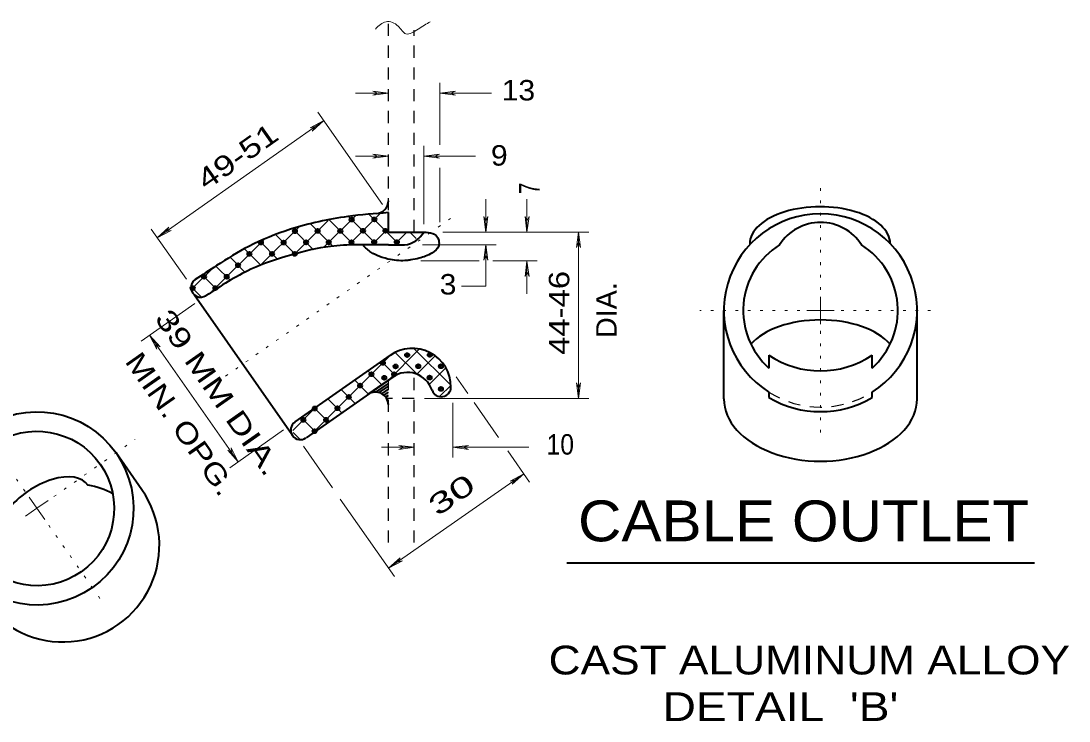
# Model space of a CAD drawing. Extents: x 312583 to 312854, y 144419 to 144597.
# Drawn here: x 312623.25 to 312662.22, y 144470.63 to 144496.66 of the extents above; entities that cross this region are included whole.
import ezdxf

# ---------------------------------------------------------------- set-up
doc = ezdxf.new("R2010")
doc.units = 0
doc.header["$LTSCALE"] = 0.3
doc.header["$PDMODE"] = 32
doc.header["$PDSIZE"] = 0.15
doc.linetypes.add('DOTTED', pattern=[1.5, 0.3, -1.2])
doc.linetypes.add('SHORT_DASHED', pattern=[2.7, 1.5, -1.2])
doc.layers.add('1', color=7, linetype='Continuous', lineweight=40)
doc.layers.add('2', color=7, linetype='Continuous', lineweight=13)

msp = doc.modelspace()

# ---------------------------------------------------------------- linework, layer by layer
at = {"layer": '1', "linetype": 'SHORT_DASHED', "lineweight": 25}
for p, q in [((312636.9103, 144488.8172), (312636.9103, 144496.6219)), ((312637.8686, 144488.8172), (312637.8686, 144496.3229)), ((312637.8686, 144477.2712), (312637.8686, 144483.5579)), ((312636.9103, 144477.2712), (312636.9103, 144483.2742)), ((312637.8686, 144482.6302), (312636.9103, 144482.6302))]:
    msp.add_line(p, q, dxfattribs=at)
at = {"layer": '1', "linetype": 'DOTTED', "lineweight": 13}
msp.add_line((312639.2256, 144489.3232), (312630.8459, 144483.4506), dxfattribs=at)
at = {"layer": '1', "lineweight": 13}
for p, q in [((312634.5106, 144488.2499), (312635.6836, 144489.4229)), ((312635.4306, 144488.3266), (312636.6189, 144489.5149)), ((312636.4656, 144488.3572), (312635.4383, 144489.3846)), ((312637.3166, 144488.3496), (312636.1896, 144489.4766)), ((312632.2106, 144487.6289), (312633.5753, 144488.9936)), ((312634.1273, 144488.1579), (312633.3529, 144488.9322)), ((312633.4066, 144487.9816), (312634.6716, 144489.2466)), ((312634.8403, 144488.2882), (312634.0123, 144489.1162)), ((312635.6299, 144488.3419), (312634.7253, 144489.2542)), ((312636.3046, 144488.3572), (312636.9103, 144488.9629)), ((312630.3476, 144486.6092), (312632.3026, 144488.5566)), ((312633.4449, 144487.9892), (312632.7013, 144488.7406)), ((312637.1326, 144488.3496), (312637.6003, 144488.8172)), ((312637.9376, 144488.5719), (312637.6923, 144488.8249)), ((312632.1416, 144487.6059), (312631.5589, 144488.1886)), ((312632.7856, 144487.8129), (312632.1263, 144488.4722)), ((312631.5743, 144487.3299), (312631.0223, 144487.8819)), ((312629.6039, 144486.7012), (312630.3936, 144487.4909)), ((312631.0299, 144487.0309), (312630.5009, 144487.5522)), ((312630.5086, 144486.7012), (312629.9873, 144487.2226)), ((312629.9413, 144486.4252), (312629.5963, 144486.7702)), ((312634.0813, 144481.3269), (312637.0253, 144484.2709)), ((312636.8873, 144483.2896), (312638.0679, 144484.4702)), ((312637.9759, 144483.5349), (312637.1479, 144484.3552)), ((312639.2409, 144483.1132), (312637.8456, 144484.4932)), ((312637.1633, 144483.4889), (312636.6496, 144484.0026)), ((312637.9683, 144483.5349), (312638.6506, 144484.2172)), ((312636.6726, 144483.1362), (312636.1513, 144483.6576)), ((312638.4359, 144483.1592), (312639.0493, 144483.7726)), ((312636.1743, 144482.7912), (312635.6606, 144483.3049)), ((312638.8116, 144482.6992), (312639.2409, 144483.1286)), ((312635.6759, 144482.4386), (312635.1546, 144482.9599)), ((312633.3529, 144481.4342), (312634.2193, 144482.3006)), ((312635.1776, 144482.0936), (312634.6639, 144482.6149)), ((312634.1886, 144481.3959), (312633.6673, 144481.9172)), ((312634.6869, 144481.7409), (312634.1656, 144482.2622)), ((312633.6059, 144481.1276), (312633.3683, 144481.3652))]:
    msp.add_line(p, q, dxfattribs=at)
at = {"layer": '1'}
for p, q in [((312636.9103, 144488.8172), (312636.9103, 144489.5379)), ((312636.9103, 144488.8172), (312638.2289, 144488.8172)), ((312636.9103, 144488.3419), (312637.5083, 144488.3419)), ((312633.3223, 144481.2886), (312629.6959, 144486.4789)), ((312649.3839, 144482.6149), (312649.3839, 144485.9039)), ((312656.5676, 144482.6149), (312656.5676, 144485.9039)), ((312636.9793, 144484.2326), (312633.4373, 144481.7562)), ((312651.0629, 144483.7572), (312651.0629, 144484.2326)), ((312654.8963, 144483.7572), (312654.8963, 144484.2326)), ((312637.0789, 144483.4199), (312633.8513, 144481.1659)), ((312636.1589, 144482.7836), (312637.0789, 144483.4199)), ((312636.4426, 144482.8679), (312636.9103, 144483.1899)), ((312636.5729, 144482.8449), (312636.9103, 144483.0826)), ((312636.6726, 144482.8066), (312636.9103, 144482.9752)), ((312636.7493, 144482.7452), (312636.9103, 144482.8602)), ((312636.8106, 144482.6839), (312636.9103, 144482.7529)), ((312651.0629, 144482.6609), (312651.0629, 144482.8679)), ((312654.8963, 144482.6609), (312654.8963, 144482.8679)), ((312636.8643, 144482.5996), (312636.9103, 144482.6379)), ((312627.7486, 144479.2339), (312626.7903, 144480.6062))]:
    msp.add_line(p, q, dxfattribs=at)
for centre, radius, start, end in [((312636.4311, 144489.9807), 0.4792, 274.52387, 0), ((312652.9758, 144485.9001), 3.5918, 302.26476, 237.73524), ((312652.9758, 144487.3632), 1.8105, 32.57755, 147.42245), ((312637.3862, 144489.3031), 0.9728, 277.20711, 330.03225), ((312652.9758, 144485.9001), 2.875, 122.03776, 228.18882), ((312652.9758, 144485.9001), 2.875, 311.81031, 57.96224), ((312629.9297, 144486.7525), 0.3605, 125.00164, 305.00164), ((312637.7996, 144483.0535), 1.4375, 0, 125.01416), ((312652.9758, 144487.1164), 3.4627, 236.39125, 303.60875), ((312637.6252, 144482.6367), 0.9583, 18.24978, 124.99202), ((312636.4311, 144482.3864), 0.4792, 0, 125.00321), ((312638.8768, 144483.0519), 0.3603, 198.353, 0), ((312652.9758, 144485.9001), 3.7626, 239.38652, 300.62404), ((312633.6404, 144481.4572), 0.3605, 125.04193, 305.04193)]:
    msp.add_arc(centre, radius, start, end, dxfattribs=at)
at = {"layer": '1', "linetype": 'SHORT_DASHED', "lineweight": 25}
msp.add_arc((312652.9758, 144485.9001), 3.5918, 237.73524, 302.26476, dxfattribs=at)
at = {"layer": '1'}
for centre, major_axis, ratio, start_param, end_param in [((312652.9547, 144488.3764), (2.6124, 0.0038), 0.5283, 6.2831853, 9.424778), ((312652.9758, 144483.9527), (-2.8731, 0), 0.555704, 3.5912894, 5.8336047), ((312652.9758, 144482.6111), (-3.5918, 0), 0.64461, 6.2831853, 9.424778), ((312624.0993, 144478.2852), (-1.6368, -1.1251), 0.537251, 3.1255912, 6.2961342), ((312624.8046, 144477.1658), (-2.9425, -2.0626), 0.999869, 0.0001305, 3.1417232), ((312625.2761, 144476.5716), (-2.3521, -1.6486), 0.999836, 3.598371, 3.9338982)]:
    msp.add_ellipse(centre, major_axis=major_axis, ratio=ratio, start_param=start_param, end_param=end_param, dxfattribs=at)
for major_axis, ratio in [((-2.9425, -2.0626), 0.999869), ((-2.3521, -1.6486), 0.999836)]:
    msp.add_ellipse((312623.8424, 144478.5382), major_axis=major_axis, ratio=ratio, dxfattribs=at)
for points in [[(312636.9103, 144489.5379), (312635.3999, 144489.3922), (312633.2686, 144488.9169), (312631.7199, 144488.2806), (312630.5239, 144487.5676), (312629.7266, 144487.0462)], [(312638.2289, 144488.8172), (312638.5586, 144488.7636), (312638.6813, 144488.6869), (312638.7809, 144488.3036), (312638.5279, 144488.0352), (312638.0526, 144487.8436), (312637.7459, 144487.7822), (312637.5926, 144487.7592), (312636.9946, 144487.7899), (312636.5806, 144487.9049), (312636.2586, 144488.0659), (312635.9673, 144488.3266)], [(312636.9103, 144488.3419), (312635.7296, 144488.3419), (312634.7559, 144488.2806), (312633.2839, 144487.9586), (312631.7966, 144487.4296), (312630.1406, 144486.4559)]]:
    msp.add_spline(points, degree=3, dxfattribs=at)
for p in [(312635.5456, 144489.2772), (312636.3889, 144489.2849), (312634.2806, 144488.8556), (312635.1239, 144488.8556), (312635.9673, 144488.8632), (312636.8029, 144488.8632), (312633.4373, 144488.8479), (312632.1723, 144488.4262), (312633.0156, 144488.4262), (312633.8513, 144488.4339), (312634.6946, 144488.4339), (312635.5379, 144488.4339), (312636.3813, 144488.4416), (312637.2246, 144488.4416), (312631.7429, 144488.0046), (312632.5863, 144488.0046), (312633.4296, 144488.0046), (312631.3213, 144487.5829), (312630.0563, 144487.1536), (312630.8996, 144487.1536), (312629.6346, 144486.7319), (312630.4779, 144486.7319), (312637.6079, 144484.2402), (312638.4513, 144484.2479), (312636.7033, 144483.9489), (312637.1786, 144483.8186), (312638.0219, 144483.8262), (312638.8653, 144483.8262), (312636.2816, 144483.5272), (312636.7569, 144483.3969), (312637.1249, 144483.5272), (312638.4436, 144483.4046), (312635.8599, 144483.1056), (312635.4383, 144482.6839), (312638.8653, 144482.9829), (312634.1733, 144482.2546), (312635.0166, 144482.2622), (312633.7516, 144481.8329), (312634.5949, 144481.8329), (312634.1656, 144481.4112)]:
    msp.add_point(p, dxfattribs=at)
at = {"layer": '2'}
for p, q in [((312636.3353, 144494.0536), (312636.5193, 144493.9769)), ((312636.9103, 144493.9769), (312636.3353, 144494.0536)), ((312638.8269, 144494.3602), (312638.8269, 144492.0602)), ((312638.8269, 144493.9769), (312639.4096, 144494.0536)), ((312639.4096, 144494.0536), (312639.2256, 144493.9769)), ((312636.9103, 144493.9769), (312635.6913, 144493.9769)), ((312636.3353, 144493.9079), (312636.5193, 144493.9769)), ((312636.9103, 144493.9769), (312636.3353, 144493.9079)), ((312638.8269, 144493.9769), (312640.7436, 144493.9769)), ((312638.8269, 144493.9769), (312639.4096, 144493.9079)), ((312639.4096, 144493.9079), (312639.2256, 144493.9769)), ((312636.6956, 144489.8446), (312634.2883, 144493.2716)), ((312628.3159, 144488.6026), (312634.5106, 144492.9572)), ((312634.5106, 144492.9572), (312633.9969, 144492.6889)), ((312634.5106, 144492.9572), (312634.0736, 144492.5662)), ((312633.9969, 144492.6889), (312634.1886, 144492.7349)), ((312634.0736, 144492.5662), (312634.1886, 144492.7349)), ((312636.3353, 144491.7076), (312636.5193, 144491.6386)), ((312636.9103, 144491.6386), (312636.3353, 144491.7076)), ((312638.2289, 144492.0219), (312638.2289, 144489.1086)), ((312638.2289, 144491.6386), (312638.8116, 144491.7076)), ((312638.8116, 144491.7076), (312638.6276, 144491.6386)), ((312636.9103, 144491.6386), (312635.6913, 144491.6386)), ((312636.3353, 144491.5619), (312636.5193, 144491.6386)), ((312636.9103, 144491.6386), (312636.3353, 144491.5619)), ((312638.2289, 144491.6386), (312640.1456, 144491.6386)), ((312638.2289, 144491.6386), (312638.8116, 144491.5619)), ((312638.8116, 144491.5619), (312638.6276, 144491.6386)), ((312638.8269, 144491.2092), (312638.8269, 144489.1776)), ((312640.5289, 144488.8172), (312640.5289, 144490.0439)), ((312642.0623, 144488.8172), (312642.0623, 144490.0439)), ((312640.4599, 144489.3999), (312640.5289, 144489.2159)), ((312640.5289, 144488.8172), (312640.4599, 144489.3999)), ((312640.6056, 144489.3999), (312640.5289, 144489.2159)), ((312640.5289, 144488.8172), (312640.6056, 144489.3999)), ((312641.9933, 144489.3999), (312642.0623, 144489.2159)), ((312642.0623, 144488.8172), (312641.9933, 144489.3999)), ((312642.1389, 144489.3999), (312642.0623, 144489.2159)), ((312642.0623, 144488.8172), (312642.1389, 144489.3999)), ((312628.3159, 144488.6026), (312628.7529, 144488.9936)), ((312628.7529, 144488.9936), (312628.6379, 144488.8326)), ((312629.4046, 144487.0616), (312628.0936, 144488.9169)), ((312628.3159, 144488.6026), (312628.8296, 144488.8786)), ((312628.8296, 144488.8786), (312628.6379, 144488.8326)), ((312638.9343, 144488.8172), (312644.3623, 144488.8172)), ((312643.9789, 144488.8172), (312643.9099, 144488.2422)), ((312643.9789, 144488.8172), (312643.9789, 144482.6302)), ((312643.9789, 144488.8172), (312644.0556, 144488.2422)), ((312638.1829, 144488.3419), (312640.9123, 144488.3419)), ((312640.5289, 144488.3419), (312640.4599, 144487.7669)), ((312640.5289, 144488.3419), (312640.5289, 144486.8086)), ((312640.5289, 144488.3419), (312640.6056, 144487.7669)), ((312643.9099, 144488.2422), (312643.9789, 144488.4262)), ((312644.0556, 144488.2422), (312643.9789, 144488.4262)), ((312640.4599, 144487.7669), (312640.5289, 144487.9509)), ((312640.6056, 144487.7669), (312640.5289, 144487.9509)), ((312638.1139, 144487.7439), (312640.2836, 144487.7439)), ((312640.7973, 144487.7439), (312642.4456, 144487.7439)), ((312642.0623, 144487.7362), (312641.9933, 144487.1612)), ((312642.0623, 144487.7362), (312642.0623, 144486.5172)), ((312642.0623, 144487.7362), (312642.1389, 144487.1612)), ((312641.9933, 144487.1612), (312642.0623, 144487.3452)), ((312642.1389, 144487.1612), (312642.0623, 144487.3452)), ((312640.5289, 144486.8086), (312639.6243, 144486.8086)), ((312652.9796, 144485.9039), (312652.9796, 144486.4099)), ((312652.9796, 144485.9039), (312652.9796, 144486.4099)), ((312629.7113, 144486.1569), (312627.7179, 144484.7616)), ((312652.9796, 144485.9039), (312652.4659, 144485.9039)), ((312652.9796, 144485.9039), (312653.4856, 144485.9039)), ((312652.9796, 144485.9039), (312652.9796, 144485.3902)), ((312628.0323, 144484.9762), (312631.3289, 144480.2766)), ((312628.0323, 144484.9762), (312628.3006, 144484.4626)), ((312628.0323, 144484.9762), (312628.4233, 144484.5469)), ((312628.3006, 144484.4626), (312628.2546, 144484.6542)), ((312628.4233, 144484.5469), (312628.2546, 144484.6542)), ((312639.4326, 144483.4352), (312639.8619, 144482.8142)), ((312643.9099, 144483.2129), (312643.9789, 144483.0289)), ((312643.9789, 144482.6302), (312643.9099, 144483.2129)), ((312644.0556, 144483.2129), (312643.9789, 144483.0289)), ((312643.9789, 144482.6302), (312644.0556, 144483.2129)), ((312638.2519, 144482.6302), (312644.3623, 144482.6302)), ((312639.3099, 144482.4692), (312639.3099, 144480.4299)), ((312640.0996, 144482.4769), (312641.0043, 144481.1812)), ((312633.0079, 144481.4572), (312631.0146, 144480.0542)), ((312631.0606, 144480.7902), (312631.1066, 144480.5986)), ((312631.3289, 144480.2766), (312631.0606, 144480.7902)), ((312633.7516, 144480.8592), (312634.8326, 144479.3029)), ((312637.8763, 144480.8132), (312636.6573, 144480.8132)), ((312637.3013, 144480.8822), (312637.4853, 144480.8132)), ((312637.8763, 144480.8132), (312637.3013, 144480.8822)), ((312637.3013, 144480.7366), (312637.4853, 144480.8132)), ((312637.8763, 144480.8132), (312637.3013, 144480.7366)), ((312639.3099, 144480.8132), (312639.8926, 144480.8822)), ((312639.3099, 144480.8132), (312642.1313, 144480.8132)), ((312639.3099, 144480.8132), (312639.8926, 144480.7366)), ((312639.8926, 144480.8822), (312639.7086, 144480.8132)), ((312639.8926, 144480.7366), (312639.7086, 144480.8132)), ((312630.9379, 144480.7059), (312631.1066, 144480.5986)), ((312631.3289, 144480.2766), (312630.9379, 144480.7059)), ((312641.3493, 144480.6829), (312642.1619, 144479.5176)), ((312636.9179, 144476.3206), (312641.9473, 144479.8319)), ((312641.9473, 144479.8319), (312641.4336, 144479.5559)), ((312641.4336, 144479.5559), (312641.6253, 144479.6019)), ((312641.9473, 144479.8319), (312641.5103, 144479.4409)), ((312641.5103, 144479.4409), (312641.6253, 144479.6019)), ((312623.8463, 144478.5439), (312623.5549, 144478.9579)), ((312623.8463, 144478.5439), (312623.5549, 144478.9579)), ((312623.8463, 144478.5439), (312624.2603, 144478.8352)), ((312635.1163, 144478.8889), (312637.1326, 144476.0062)), ((312623.8463, 144478.5439), (312623.4246, 144478.2526)), ((312623.8463, 144478.5439), (312624.1376, 144478.1222)), ((312636.9179, 144476.3206), (312637.3473, 144476.7039)), ((312636.9179, 144476.3206), (312637.4316, 144476.5889)), ((312637.3473, 144476.7039), (312637.2399, 144476.5429)), ((312637.4316, 144476.5889), (312637.2399, 144476.5429))]:
    msp.add_line(p, q, dxfattribs=at)
at = {"layer": '2', "linetype": 'DOTTED'}
for p, q in [((312652.9796, 144486.6706), (312652.9796, 144490.7416)), ((312652.2129, 144485.9039), (312648.4946, 144485.9039)), ((312653.7463, 144485.9039), (312657.4186, 144485.9039)), ((312652.9796, 144485.1372), (312652.9796, 144481.0892)), ((312623.4016, 144479.1726), (312621.3009, 144482.1779)), ((312624.4749, 144478.9809), (312627.4879, 144481.0969)), ((312624.2833, 144477.9152), (312626.3686, 144474.9329))]:
    msp.add_line(p, q, dxfattribs=at)
at = {"layer": '2', "lineweight": 40}
msp.add_line((312643.548, 144476.5122), (312660.9328, 144476.5122), dxfattribs=at)
at = {"layer": '2'}
msp.add_spline([(312636.4273, 144496.3612), (312636.8259, 144496.6372), (312637.2783, 144496.4686), (312637.5619, 144496.1849), (312638.0143, 144496.3612), (312638.4666, 144496.6372)], degree=3, dxfattribs=at)

# ---------------------------------------------------------------- texts
for s, height, width, p in [('13 ', 0.76, 1.1, (312641.1224, 144493.7092)), ('9 ', 0.76, 1.1, (312640.7225, 144491.2859)), ('3 ', 0.76, 1.1, (312638.8166, 144486.4937)), ('10', 0.76, 0.9, (312642.7933, 144480.5412)), ('CABLE OUTLET', 1.52, 1.1, (312643.9597, 144477.3158)), ('CAST ALUMINUM ALLOY', 1.07, 1.15, (312642.8675, 144472.367)), ("DETAIL  'B'", 1.07, 1.2, (312647.103, 144470.6346))]:
    msp.add_text(s, height=height, dxfattribs=dict(at, width=width)).set_placement(p)
for s, rotation, width, p in [('49-51 ', 35.127, 1.3, (312630.1351, 144490.3464)), ('7', 90, 0.75, (312642.5293, 144490.2243)), ('44-46', 90, 1.2, (312643.6362, 144484.2504)), ('DIA.', 90, 1.05, (312645.3961, 144484.8759)), ('39 MM DIA.', 305.032, 1.35, (312628.1953, 144485.6023)), ('MIN. OPG.', 305.063, 1.25, (312627.0884, 144484.0047)), ('30 ', 34.811, 1.6, (312638.7353, 144478.2216))]:
    msp.add_text(s, height=0.76, rotation=rotation, dxfattribs=dict(at, width=width)).set_placement(p)

doc.saveas('drawing.dxf')
